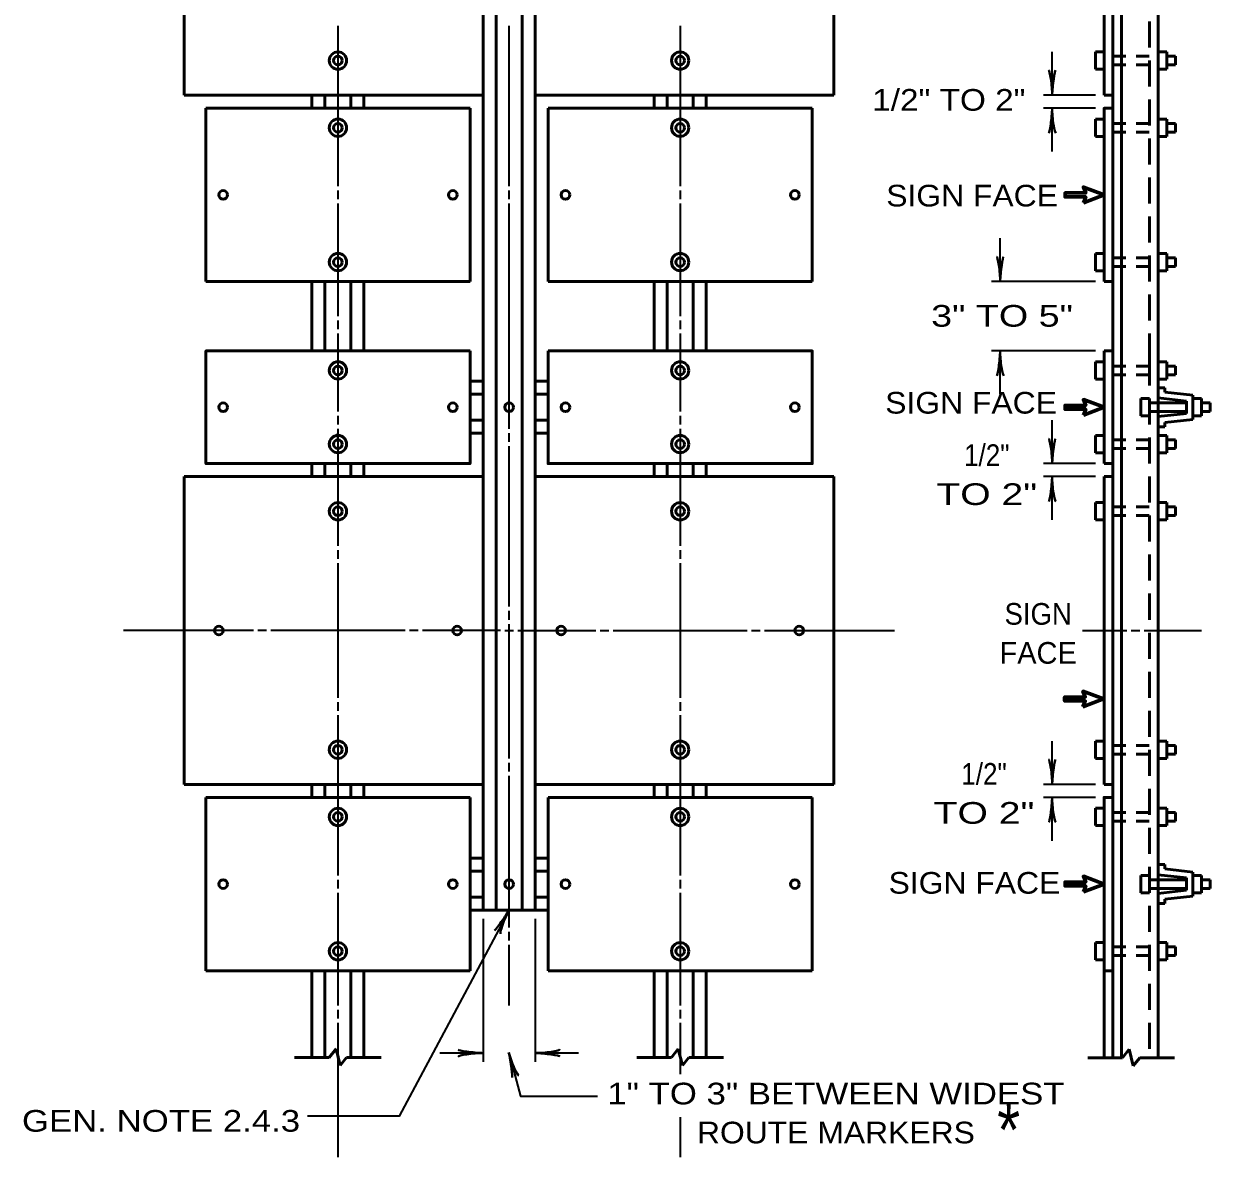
# Model space of a CAD drawing. Extents: x -45 to 635, y -382 to 59.
# Drawn here: x 141.3 to 278.3, y -273.6 to -142.8 of the extents above; entities that cross this region are included whole.
import ezdxf
from ezdxf.enums import TextEntityAlignment as Align

# ---------------------------------------------------------------- set-up
doc = ezdxf.new("R2010")
doc.units = 0
doc.linetypes.add('MEDIUM_DASHED', pattern=[4.5, 3, -1.5])
doc.linetypes.add('SHORT_DASHED', pattern=[2.7, 1.5, -1.2])
doc.layers.add('1', color=7, linetype='Continuous', lineweight=53)

msp = doc.modelspace()

# ---------------------------------------------------------------- linework, layer by layer
at = {"layer": '1'}
for p, q in [((194.367, -202.09), (194.367, -93.09)), ((195.867, -202.09), (195.867, -93.09)), ((198.867, -202.09), (198.867, -93.09)), ((200.367, -202.09), (200.367, -93.09)), ((268.058, -102.09), (268.058, -181.59)), ((272.308, -102.09), (272.308, -181.59)), ((159.867, -115.59), (159.867, -151.09)), ((234.867, -115.59), (234.867, -151.09)), ((266.058, -115.59), (266.058, -151.09)), ((265.058, -148.09), (265.058, -146.09)), ((265.058, -146.09), (266.058, -146.09)), ((273.308, -146.09), (272.308, -146.09)), ((273.308, -148.09), (273.308, -146.09)), ((273.308, -146.59), (274.308, -146.59)), ((273.308, -147.59), (274.308, -147.59)), ((274.308, -147.59), (274.308, -146.59)), ((265.058, -148.09), (266.058, -148.09)), ((273.308, -148.09), (272.308, -148.09)), ((194.367, -151.09), (159.867, -151.09)), ((174.617, -152.59), (174.617, -151.09)), ((176.117, -152.59), (176.117, -151.09)), ((179.117, -152.59), (179.117, -151.09)), ((180.617, -152.59), (180.617, -151.09)), ((234.867, -151.09), (200.367, -151.09)), ((214.117, -152.59), (214.117, -151.09)), ((215.617, -152.59), (215.617, -151.09)), ((218.617, -152.59), (218.617, -151.09)), ((220.117, -152.59), (220.117, -151.09)), ((266.058, -151.09), (267.058, -151.09)), ((192.867, -152.59), (162.367, -152.59)), ((162.367, -152.59), (162.367, -172.59)), ((192.867, -172.59), (192.867, -152.59)), ((232.367, -152.59), (201.867, -152.59)), ((201.867, -152.59), (201.867, -172.59)), ((232.367, -172.59), (232.367, -152.59)), ((265.058, -155.84), (265.058, -153.84)), ((265.058, -153.84), (266.058, -153.84)), ((273.308, -153.84), (272.308, -153.84)), ((273.308, -155.84), (273.308, -153.84)), ((273.308, -154.34), (274.308, -154.34)), ((274.308, -155.34), (274.308, -154.34)), ((265.058, -155.84), (266.058, -155.84)), ((273.308, -155.84), (272.308, -155.84)), ((273.308, -155.34), (274.308, -155.34)), ((265.058, -171.34), (265.058, -169.34)), ((265.058, -169.34), (266.058, -169.34)), ((273.308, -169.34), (272.308, -169.34)), ((273.308, -171.34), (273.308, -169.34)), ((273.308, -169.84), (274.308, -169.84)), ((273.308, -170.84), (274.308, -170.84)), ((274.308, -170.84), (274.308, -169.84)), ((265.058, -171.34), (266.058, -171.34)), ((273.308, -171.34), (272.308, -171.34)), ((192.867, -172.59), (162.367, -172.59)), ((174.617, -172.59), (174.617, -180.59)), ((176.117, -172.59), (176.117, -180.59)), ((179.117, -172.59), (179.117, -180.59)), ((180.617, -172.59), (180.617, -180.59)), ((232.367, -172.59), (201.867, -172.59)), ((214.117, -172.59), (214.117, -180.59)), ((215.617, -172.59), (215.617, -180.59)), ((218.617, -172.59), (218.617, -180.59)), ((220.117, -172.59), (220.117, -180.59)), ((266.058, -172.59), (267.058, -172.59)), ((266.058, -180.59), (266.058, -193.59)), ((266.058, -180.59), (267.058, -180.59)), ((265.058, -181.84), (265.058, -183.84)), ((265.058, -181.84), (266.058, -181.84)), ((268.058, -181.59), (268.058, -262.11)), ((272.308, -181.59), (272.308, -262.11)), ((273.308, -181.84), (272.308, -181.84)), ((273.308, -181.84), (273.308, -183.84)), ((273.308, -182.34), (274.308, -182.34)), ((273.308, -183.34), (274.308, -183.34)), ((274.308, -182.34), (274.308, -183.34)), ((192.867, -184.09), (194.367, -184.09)), ((201.867, -184.09), (200.367, -184.09)), ((265.058, -183.84), (266.058, -183.84)), ((273.308, -183.84), (272.308, -183.84)), ((273.058, -184.84), (272.308, -184.84)), ((273.058, -184.84), (273.058, -185.34)), ((192.867, -185.59), (194.367, -185.59)), ((201.867, -185.59), (200.367, -185.59)), ((270.308, -186.09), (270.308, -188.09)), ((270.308, -186.09), (271.308, -186.09)), ((272.308, -186.011), (275.558, -186.372)), ((273.058, -185.34), (276.308, -185.701)), ((276.308, -185.701), (276.308, -188.479)), ((277.308, -186.09), (276.308, -186.09)), ((277.308, -186.09), (277.308, -188.09)), ((272.308, -186.59), (275.558, -186.59)), ((272.308, -187.59), (275.558, -187.59)), ((275.558, -186.372), (275.558, -187.808)), ((277.308, -186.59), (278.308, -186.59)), ((277.308, -187.59), (278.308, -187.59)), ((278.308, -186.59), (278.308, -187.59)), ((192.867, -188.59), (194.367, -188.59)), ((201.867, -188.59), (200.367, -188.59)), ((270.308, -188.09), (271.308, -188.09)), ((272.308, -188.169), (275.558, -187.808)), ((273.058, -188.84), (276.308, -188.479)), ((273.058, -188.84), (273.058, -189.34)), ((277.308, -188.09), (276.308, -188.09)), ((192.867, -190.09), (194.367, -190.09)), ((201.867, -190.09), (200.367, -190.09)), ((265.058, -190.34), (265.058, -192.34)), ((265.058, -190.34), (266.058, -190.34)), ((273.058, -189.34), (272.308, -189.34)), ((273.308, -190.34), (272.308, -190.34)), ((273.308, -190.34), (273.308, -192.34)), ((273.308, -190.84), (274.308, -190.84)), ((274.308, -190.84), (274.308, -191.84)), ((265.058, -192.34), (266.058, -192.34)), ((273.308, -192.34), (272.308, -192.34)), ((273.308, -191.84), (274.308, -191.84)), ((174.617, -193.59), (174.617, -195.09)), ((176.117, -193.59), (176.117, -195.09)), ((179.117, -193.59), (179.117, -195.09)), ((180.617, -193.59), (180.617, -195.09)), ((214.117, -193.59), (214.117, -195.09)), ((215.617, -193.59), (215.617, -195.09)), ((218.617, -193.59), (218.617, -195.09)), ((220.117, -193.59), (220.117, -195.09)), ((266.058, -193.59), (267.058, -193.59)), ((159.867, -195.09), (194.367, -195.09)), ((159.867, -195.09), (159.867, -230.59)), ((194.367, -195.09), (194.367, -230.59)), ((234.867, -195.09), (200.367, -195.09)), ((200.367, -195.09), (200.367, -230.59)), ((234.867, -195.09), (234.867, -230.59)), ((266.058, -195.09), (266.058, -230.59)), ((266.058, -195.09), (267.058, -195.09)), ((265.058, -198.09), (265.058, -200.09)), ((265.058, -198.09), (266.058, -198.09)), ((273.308, -198.09), (272.308, -198.09)), ((273.308, -198.09), (273.308, -200.09)), ((273.308, -198.59), (274.308, -198.59)), ((274.308, -198.59), (274.308, -199.59)), ((273.308, -199.59), (274.308, -199.59)), ((265.058, -200.09), (266.058, -200.09)), ((273.308, -200.09), (272.308, -200.09)), ((195.867, -237.59), (195.867, -202.09)), ((198.867, -237.59), (198.867, -202.09)), ((200.367, -237.59), (200.367, -202.09)), ((265.058, -227.59), (265.058, -225.59)), ((265.058, -225.59), (266.058, -225.59)), ((273.308, -225.59), (272.308, -225.59)), ((273.308, -227.59), (273.308, -225.59)), ((273.308, -226.09), (274.308, -226.09)), ((273.308, -227.09), (274.308, -227.09)), ((274.308, -227.09), (274.308, -226.09)), ((265.058, -227.59), (266.058, -227.59)), ((273.308, -227.59), (272.308, -227.59)), ((159.867, -230.59), (194.367, -230.59)), ((174.617, -232.09), (174.617, -230.59)), ((176.117, -232.09), (176.117, -230.59)), ((179.117, -232.09), (179.117, -230.59)), ((180.617, -232.09), (180.617, -230.59)), ((194.367, -245.09), (194.367, -230.59)), ((234.867, -230.59), (200.367, -230.59)), ((214.117, -232.09), (214.117, -230.59)), ((215.617, -232.09), (215.617, -230.59)), ((218.617, -232.09), (218.617, -230.59)), ((220.117, -232.09), (220.117, -230.59)), ((266.058, -230.59), (267.058, -230.59)), ((162.367, -232.09), (192.867, -232.09)), ((162.367, -252.09), (162.367, -232.09)), ((192.867, -232.09), (192.867, -252.09)), ((232.367, -232.09), (201.867, -232.09)), ((201.867, -232.09), (201.867, -252.09)), ((232.367, -252.09), (232.367, -232.09)), ((265.058, -235.34), (265.058, -233.34)), ((265.058, -233.34), (266.058, -233.34)), ((273.308, -233.34), (272.308, -233.34)), ((273.308, -235.34), (273.308, -233.34)), ((273.308, -233.84), (274.308, -233.84)), ((274.308, -234.84), (274.308, -233.84)), ((265.058, -235.34), (266.058, -235.34)), ((273.308, -235.34), (272.308, -235.34)), ((273.308, -234.84), (274.308, -234.84)), ((195.867, -245.09), (195.867, -237.59)), ((198.867, -245.09), (198.867, -237.59)), ((200.367, -245.09), (200.367, -237.59)), ((192.867, -239.09), (194.367, -239.09)), ((201.867, -239.09), (200.367, -239.09)), ((192.867, -240.59), (194.367, -240.59)), ((201.867, -240.59), (200.367, -240.59)), ((273.058, -239.84), (272.308, -239.84)), ((272.308, -241.011), (275.558, -241.372)), ((273.058, -239.84), (273.058, -240.34)), ((273.058, -240.34), (276.308, -240.701)), ((276.308, -240.701), (276.308, -243.479)), ((270.308, -241.09), (270.308, -243.09)), ((270.308, -241.09), (271.308, -241.09)), ((272.308, -241.59), (275.558, -241.59)), ((275.558, -241.372), (275.558, -242.808)), ((277.308, -241.09), (276.308, -241.09)), ((277.308, -241.09), (277.308, -243.09)), ((277.308, -241.59), (278.308, -241.59)), ((278.308, -241.59), (278.308, -242.59)), ((192.867, -243.59), (194.367, -243.59)), ((201.867, -243.59), (200.367, -243.59)), ((270.308, -243.09), (271.308, -243.09)), ((272.308, -242.59), (275.558, -242.59)), ((272.308, -243.169), (275.558, -242.808)), ((273.058, -243.84), (276.308, -243.479)), ((277.308, -243.09), (276.308, -243.09)), ((277.308, -242.59), (278.308, -242.59)), ((192.867, -245.09), (201.867, -245.09)), ((273.058, -244.34), (272.308, -244.34)), ((273.058, -243.84), (273.058, -244.34)), ((265.058, -250.84), (265.058, -248.84)), ((265.058, -248.84), (266.058, -248.84)), ((273.308, -248.84), (272.308, -248.84)), ((273.308, -250.84), (273.308, -248.84)), ((273.308, -249.34), (274.308, -249.34)), ((273.308, -250.34), (274.308, -250.34)), ((274.308, -250.34), (274.308, -249.34)), ((265.058, -250.84), (266.058, -250.84)), ((273.308, -250.84), (272.308, -250.84)), ((162.367, -252.09), (192.867, -252.09)), ((174.617, -252.09), (174.617, -262.09)), ((176.117, -252.09), (176.117, -262.09)), ((179.117, -252.09), (179.117, -262.09)), ((180.617, -252.09), (180.617, -262.09)), ((232.367, -252.09), (201.867, -252.09)), ((214.117, -252.09), (214.117, -262.09)), ((215.617, -252.09), (215.617, -262.09)), ((218.617, -252.09), (218.617, -262.09)), ((220.117, -252.09), (220.117, -262.09)), ((266.058, -252.09), (267.058, -252.09)), ((177.396, -261.116), (176.617, -262.09)), ((177.396, -261.116), (177.871, -263.022)), ((216.896, -261.116), (216.117, -262.09)), ((216.896, -261.116), (217.371, -263.022)), ((268.946, -261.157), (268.167, -262.131)), ((268.946, -261.157), (269.421, -263.063)), ((172.617, -262.09), (176.617, -262.09)), ((178.617, -262.09), (177.871, -263.022)), ((178.617, -262.09), (182.617, -262.09)), ((212.117, -262.09), (216.117, -262.09)), ((218.117, -262.09), (217.371, -263.022)), ((218.117, -262.09), (222.117, -262.09)), ((264.167, -262.131), (268.167, -262.131)), ((270.167, -262.131), (269.421, -263.063)), ((270.167, -262.131), (274.167, -262.131))]:
    msp.add_line(p, q, dxfattribs=at)
at = {"layer": '1', "linetype": 'MEDIUM_DASHED'}
for p, q in [((271.308, -102.09), (271.308, -181.59)), ((271.308, -181.59), (271.308, -262.11))]:
    msp.add_line(p, q, dxfattribs=at)
at = {"layer": '1', "lineweight": 35}
for p, q in [((177.617, -143.09), (177.617, -161.59)), ((197.367, -161.59), (197.367, -143.09)), ((217.117, -143.09), (217.117, -161.59)), ((260.058, -151.09), (260.058, -146.09)), ((265.058, -151.09), (259.058, -151.09)), ((265.058, -152.59), (259.058, -152.59)), ((260.058, -157.59), (260.058, -152.59)), ((177.617, -162.09), (177.617, -163.09)), ((197.367, -163.09), (197.367, -162.09)), ((217.117, -162.09), (217.117, -163.09)), ((177.617, -163.59), (177.617, -176.59)), ((197.367, -189.59), (197.367, -163.59)), ((217.117, -163.59), (217.117, -176.59)), ((254.058, -172.59), (254.058, -167.59)), ((265.058, -172.59), (253.058, -172.59)), ((177.617, -177.09), (177.617, -178.09)), ((217.117, -177.09), (217.117, -178.09)), ((177.617, -178.59), (177.617, -187.59)), ((217.117, -178.59), (217.117, -187.59)), ((265.058, -180.59), (253.058, -180.59)), ((254.058, -185.59), (254.058, -180.59)), ((177.617, -188.09), (177.617, -189.09)), ((217.117, -188.09), (217.117, -189.09)), ((260.058, -193.59), (260.058, -188.59)), ((177.617, -189.59), (177.617, -203.09)), ((177.617, -191.09), (177.617, -190.09)), ((197.367, -191.09), (197.367, -190.09)), ((217.117, -189.59), (217.117, -203.09)), ((197.367, -210.09), (197.367, -191.59)), ((265.058, -193.59), (259.058, -193.59)), ((265.058, -195.09), (259.058, -195.09)), ((260.058, -200.09), (260.058, -195.09)), ((177.617, -203.59), (177.617, -204.59)), ((217.117, -203.59), (217.117, -204.59)), ((177.617, -205.09), (177.617, -220.59)), ((217.117, -205.09), (217.117, -220.59)), ((197.367, -211.59), (197.367, -210.59)), ((197.367, -227.59), (197.367, -212.09)), ((167.867, -212.84), (152.867, -212.84)), ((169.367, -212.84), (168.367, -212.84)), ((185.367, -212.84), (169.867, -212.84)), ((186.867, -212.84), (185.867, -212.84)), ((195.367, -212.84), (187.367, -212.84)), ((194.248, -212.84), (192.367, -212.84)), ((196.367, -212.84), (195.367, -212.84)), ((196.867, -212.84), (197.867, -212.84)), ((198.367, -212.84), (199.367, -212.84)), ((199.367, -212.84), (207.367, -212.84)), ((200.486, -212.84), (202.367, -212.84)), ((207.867, -212.84), (208.867, -212.84)), ((209.367, -212.84), (224.867, -212.84)), ((225.367, -212.84), (226.367, -212.84)), ((226.867, -212.84), (241.867, -212.84)), ((263.558, -212.84), (268.683, -212.84)), ((269.183, -212.84), (270.183, -212.84)), ((270.683, -212.84), (277.308, -212.84)), ((177.617, -221.09), (177.617, -222.09)), ((217.117, -221.09), (217.117, -222.09)), ((177.617, -222.59), (177.617, -241.09)), ((217.117, -222.59), (217.117, -241.09)), ((260.058, -230.59), (260.058, -225.59)), ((197.367, -229.09), (197.367, -228.09)), ((197.367, -247.09), (197.367, -229.59)), ((265.058, -230.59), (259.058, -230.59)), ((265.058, -232.09), (259.058, -232.09)), ((260.058, -237.09), (260.058, -232.09)), ((177.617, -241.59), (177.617, -242.59)), ((217.117, -241.59), (217.117, -242.59)), ((177.617, -243.09), (177.617, -256.09)), ((217.117, -243.09), (217.117, -256.09)), ((194.367, -246.09), (194.367, -262.59)), ((200.367, -246.09), (200.367, -262.59)), ((197.367, -248.59), (197.367, -247.59)), ((197.367, -256.09), (197.367, -249.09)), ((177.617, -256.59), (177.617, -257.59)), ((217.117, -256.59), (217.117, -257.59)), ((217.117, -258.09), (217.117, -264.019)), ((194.367, -261.59), (189.367, -261.59)), ((205.367, -261.59), (200.367, -261.59)), ((217.117, -268.982), (217.117, -273.61))]:
    msp.add_line(p, q, dxfattribs=at)
at = {"layer": '1', "linetype": 'SHORT_DASHED'}
for p, q in [((267.058, -146.59), (272.308, -146.59)), ((267.058, -147.59), (272.308, -147.59)), ((267.058, -154.34), (272.308, -154.34)), ((267.058, -155.34), (272.308, -155.34)), ((267.058, -169.84), (272.308, -169.84)), ((267.058, -170.84), (272.308, -170.84)), ((267.058, -182.34), (272.308, -182.34)), ((267.058, -183.34), (272.308, -183.34)), ((272.308, -186.59), (271.308, -186.59)), ((272.308, -187.59), (271.308, -187.59)), ((267.058, -190.84), (272.308, -190.84)), ((267.058, -191.84), (272.308, -191.84)), ((267.058, -198.59), (272.308, -198.59)), ((267.058, -199.59), (272.308, -199.59)), ((267.058, -226.09), (272.308, -226.09)), ((267.058, -227.09), (272.308, -227.09)), ((267.058, -233.84), (272.308, -233.84)), ((267.058, -234.84), (272.308, -234.84)), ((272.308, -241.59), (271.308, -241.59)), ((272.308, -242.59), (271.308, -242.59)), ((267.058, -249.34), (272.308, -249.34)), ((267.058, -250.34), (272.308, -250.34))]:
    msp.add_line(p, q, dxfattribs=at)
at = {"layer": '1'}
for points in [[(267.058, -101.09), (267.058, -115.59), (267.058, -180.59)], [(266.058, -172.59), (266.058, -152.59), (267.058, -152.59)], [(267.058, -180.59), (267.058, -195.09), (267.058, -262.09)], [(266.058, -262.11), (266.058, -232.09), (267.058, -232.09)]]:
    msp.add_lwpolyline(points, dxfattribs=at)
at = {"layer": '1', "lineweight": 60}
for points in [[(263.673, -163.49), (266.058, -162.59), (263.673, -161.69), (263.943, -162.365), (261.558, -162.365), (261.558, -162.815), (263.943, -162.815)], [(263.673, -187.99), (266.058, -187.09), (263.673, -186.19), (263.943, -186.865), (261.558, -186.865), (261.558, -187.315), (263.943, -187.315)], [(263.605, -221.641), (265.99, -220.742), (263.605, -219.841), (263.875, -220.516), (261.49, -220.516), (261.49, -220.966), (263.875, -220.966)], [(263.673, -242.99), (266.058, -242.09), (263.673, -241.19), (263.943, -241.865), (261.558, -241.865), (261.558, -242.315), (263.943, -242.315)]]:
    msp.add_lwpolyline(points, close=True, dxfattribs=at)
at = {"layer": '1'}
for points in [[(192.867, -180.59), (162.367, -180.59), (162.367, -193.59), (192.867, -193.59)], [(201.867, -180.59), (232.367, -180.59), (232.367, -193.59), (201.867, -193.59)]]:
    msp.add_lwpolyline(points, close=True, dxfattribs=at)
at = {"layer": '1', "lineweight": 35}
for points in [[(197.367, -245.09), (184.667, -268.866), (174.098, -268.866)], [(177.617, -258.09), (177.617, -262.09), (177.617, -273.61)], [(197.324, -261.517), (198.696, -266.547), (207.566, -266.547)]]:
    msp.add_lwpolyline(points, dxfattribs=at)
at = {"layer": '1'}
for centre, radius in [((177.617, -147.09), 1), ((217.117, -147.09), 1), ((177.617, -147.09), 0.5), ((217.117, -147.09), 0.5), ((177.617, -154.84), 1), ((177.617, -154.84), 0.5), ((217.117, -154.84), 1), ((217.117, -154.84), 0.5), ((164.367, -162.59), 0.5), ((190.867, -162.59), 0.5), ((203.867, -162.59), 0.5), ((230.367, -162.59), 0.5), ((177.617, -170.34), 1), ((217.117, -170.34), 1), ((177.617, -170.34), 0.5), ((217.117, -170.34), 0.5), ((177.617, -182.84), 1), ((217.117, -182.84), 1), ((177.617, -182.84), 0.5), ((217.117, -182.84), 0.5), ((164.367, -187.09), 0.5), ((190.867, -187.09), 0.5), ((197.367, -187.09), 0.5), ((203.867, -187.09), 0.5), ((230.367, -187.09), 0.5), ((177.617, -191.34), 1), ((217.117, -191.34), 1), ((177.617, -191.34), 0.5), ((217.117, -191.34), 0.5), ((177.617, -199.09), 1), ((177.617, -199.09), 0.5), ((217.117, -199.09), 1), ((217.117, -199.09), 0.5), ((163.867, -212.84), 0.5), ((191.367, -212.84), 0.5), ((203.367, -212.84), 0.5), ((230.867, -212.84), 0.5), ((177.617, -226.59), 1), ((217.117, -226.59), 1), ((177.617, -226.59), 0.5), ((217.117, -226.59), 0.5), ((177.617, -234.34), 1), ((177.617, -234.34), 0.5), ((217.117, -234.34), 1), ((217.117, -234.34), 0.5), ((164.367, -242.09), 0.5), ((190.867, -242.09), 0.5), ((197.367, -242.09), 0.5), ((203.867, -242.09), 0.5), ((230.367, -242.09), 0.5), ((177.617, -249.84), 1), ((217.117, -249.84), 1), ((177.617, -249.84), 0.5), ((217.117, -249.84), 0.5)]:
    msp.add_circle(centre, radius, dxfattribs=at)
at = {"layer": '1', "lineweight": 40}
for centre, major_axis, ratio, start_param, end_param in [((259.782, -149.999), (0.156, -1.786), 0.122415, 0.8963533, 3.1415927), ((259.782, -149.999), (0.156, -1.786), 0.122415, 0.8963533, 3.1415927), ((260.27, -149.969), (-0.176, -1.756), 0.07063, 3.1407148, 5.41811), ((260.27, -149.969), (-0.176, -1.756), 0.07063, 3.1407148, 5.41811), ((259.847, -153.71), (0.176, 1.756), 0.07063, 3.1407148, 5.41811), ((260.335, -153.681), (-0.156, 1.786), 0.122415, 0.8963533, 3.1415927), ((253.782, -171.499), (0.156, -1.786), 0.122415, 0.8963533, 3.1415927), ((253.782, -171.499), (0.156, -1.786), 0.122415, 0.8963533, 3.1415927), ((254.27, -171.469), (-0.176, -1.756), 0.07063, 3.1407148, 5.41811), ((254.27, -171.469), (-0.176, -1.756), 0.07063, 3.1407148, 5.41811), ((253.847, -181.71), (0.176, 1.756), 0.07063, 3.1407148, 5.41811), ((253.847, -181.71), (0.176, 1.756), 0.07063, 3.1407148, 5.41811), ((254.335, -181.681), (-0.156, 1.786), 0.122415, 0.8963533, 3.1415927), ((254.335, -181.681), (-0.156, 1.786), 0.122415, 0.8963533, 3.1415927), ((259.782, -192.499), (0.156, -1.786), 0.122415, 0.8963533, 3.1415927), ((259.782, -192.499), (0.156, -1.786), 0.122415, 0.8963533, 3.1415927), ((260.27, -192.469), (-0.176, -1.756), 0.07063, 3.1407148, 5.41811), ((260.27, -192.469), (-0.176, -1.756), 0.07063, 3.1407148, 5.41811), ((259.847, -196.21), (0.176, 1.756), 0.07063, 3.1407148, 5.41811), ((260.335, -196.181), (-0.156, 1.786), 0.122415, 0.8963533, 3.1415927), ((259.782, -229.499), (0.156, -1.786), 0.122415, 0.8963533, 3.1415927), ((259.782, -229.499), (0.156, -1.786), 0.122415, 0.8963533, 3.1415927), ((260.27, -229.469), (-0.176, -1.756), 0.07063, 3.1407148, 5.41811), ((260.27, -229.469), (-0.176, -1.756), 0.07063, 3.1407148, 5.41811), ((259.847, -233.21), (0.176, 1.756), 0.07063, 3.1407148, 5.41811), ((259.847, -233.21), (0.176, 1.756), 0.07063, 3.1407148, 5.41811), ((260.335, -233.181), (-0.156, 1.786), 0.122415, 0.8963533, 3.1415927), ((260.335, -233.181), (-0.156, 1.786), 0.122415, 0.8963533, 3.1415927), ((196.653, -245.978), (0.982, 1.467), 0.07063, 3.1407148, 5.41811), ((197.097, -246.182), (0.704, 1.649), 0.122415, 0.8963533, 3.1415927), ((193.276, -261.866), (1.786, 0.156), 0.122415, 0.8963533, 3.1415927), ((193.247, -261.378), (1.756, -0.176), 0.07063, 3.1407148, 5.41811), ((197.415, -262.653), (-0.293, 1.741), 0.07063, 3.1407148, 5.41811), ((197.878, -262.497), (-0.62, 1.682), 0.122415, 0.8963533, 3.1415927), ((201.458, -261.313), (-1.786, -0.156), 0.122415, 0.8963533, 3.1415927), ((201.488, -261.801), (-1.756, 0.176), 0.07063, 3.1407148, 5.41811)]:
    msp.add_ellipse(centre, major_axis=major_axis, ratio=ratio, start_param=start_param, end_param=end_param, dxfattribs=at)

# ---------------------------------------------------------------- texts
at = {"layer": '1'}
for s, height, width, p in [('1/2" TO 2"', 2.5, 1.15, (248.132, -152.874)), ('SIGN FACE', 2.5, 1.1, (250.815, -163.922)), ('3" TO 5"', 2.5, 1.3, (254.274, -177.788)), ('SIGN FACE', 2.5, 1.1, (250.698, -187.817)), ('1/2"', 2.5, 0.9, (252.507, -193.86)), ('TO 2"', 2.5, 1.35, (252.507, -198.36)), ('SIGN', 2.5, 0.95, (258.442, -212.172)), ('1/2"', 2.5, 0.9, (252.191, -230.633)), ('TO 2"', 2.5, 1.35, (252.191, -235.133)), ('SIGN FACE', 2.5, 1.1, (251.088, -243.205)), ('1" TO 3" BETWEEN WIDEST', 2.5, 1.2, (235.095, -267.511)), ('GEN. NOTE 2.4.3', 2.5, 1.2, (157.195, -270.66)), ('*', 6, 0.85, (255.035, -273.44)), ('ROUTE MARKERS', 2.5, 1.1, (235.095, -272.011))]:
    msp.add_text(s, height=height, dxfattribs=dict(at, width=width)).set_placement(p, align=Align.CENTER)
msp.add_text('FACE', height=2.5, dxfattribs=at).set_placement((258.442, -216.672), align=Align.CENTER)

doc.saveas('drawing.dxf')
